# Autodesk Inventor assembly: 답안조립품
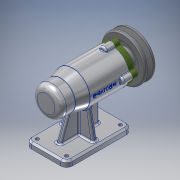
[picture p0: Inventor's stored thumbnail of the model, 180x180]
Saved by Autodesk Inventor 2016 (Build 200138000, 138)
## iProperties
Created: 2019-07
Part Number: 답안조립품
Material: 일반
Document SubType Name: Assembly
Designer: 3sil_0101
Author: 3sil_0101
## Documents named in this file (12)
- C:\Users\3sil_0101\Desktop\490704V1015\답안조립품.iam
- C:\Users\3sil_0101\Desktop\490704V1015\본체.ipt
- C:\Users\3sil_0101\Desktop\490704V1015\V벨트풀리.ipt
- C:\Users\3sil_0101\Desktop\490704V1015\멈춤나사 M3.ipt
- C:\Users\3sil_0101\Desktop\490704V1015\베어링 6004.ipt
- C:\Users\3sil_0101\Desktop\490704V1015\베어링 51202.ipt
- C:\Users\3sil_0101\Desktop\490704V1015\볼트 M4.ipt
- C:\Users\3sil_0101\Desktop\490704V1015\어댑터슬리브.ipt
- C:\Users\3sil_0101\Desktop\490704V1015\오일 실.ipt
- C:\Users\3sil_0101\Desktop\490704V1015\축.ipt
- C:\Users\3sil_0101\Desktop\490704V1015\커버.ipt
- C:\Users\3sil_0101\Desktop\490704V1015\키 5 x 5 x 16.ipt
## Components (1 placed, 1 different names)
1. V벨트풀리:1 — 각도:2
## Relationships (1: Angle 1)
- 각도:2 [Angle]: V벨트풀리:1
